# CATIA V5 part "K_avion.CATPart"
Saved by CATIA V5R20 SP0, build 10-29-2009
Part number: avion
Publications: "demi largeur balancier", "epaisseur pieces", "decalage pneu", "Plan.-100", "liaison avion 3/10", "liaison avion 24/28"
Bounding box of the stored display mesh (mm): x -130 to 30, y -769.943 to 389.943, z -50 to 50
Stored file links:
  G:\Khaled_CFAO_2011\SIL\SIL_GR2\mdardier\Khaled\CAD_ThinkMOTION\K_avion.CATPart
  G:\Khaled_CFAO_2011\SIL\SIL_GR2\mdardier\Khaled\CAD_ThinkMOTION\K_ass_tandem.CATProduct
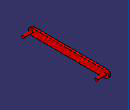
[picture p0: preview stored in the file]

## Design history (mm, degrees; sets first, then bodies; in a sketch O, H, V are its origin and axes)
External parameters (linked from other documents)
  `External.demi largeur balancier` = 50 mm
  `External.epaisseur pieces` = 30 mm
  `External.decalage pneu` = 100 mm
Set1
  Plane1 "Plan.-100": linked copy from another document
  Point1 "liaison avion 3/10": linked copy from another document
  Point2 "liaison avion 24/28": linked copy from another document
Body1 (main body)
  Sketch1 on Plane1, origin (-100, 0, 0), H (0, 1, 0), V (0, 0, 1)
    construction line L1 (-720, 0) -> (340, 0)
    point P1 (-720, 0)
    point P2 (340, 0)
    line L2 (-720, 50) -> (340, 50)
    line L3 (340, -50) -> (-720, -50)
    arc A1 centre (340, 0) radius 50 from (340, 50) to (340, -50) cw
    arc A2 centre (-720, 0) radius 50 from (-720, -50) to (-720, 50) cw
    reference projected point E1 (-720, 0) from Point1
    reference projected point E2 (340, 0) from Point2
    distance L1 L2 = 50 {= `External.demi largeur balancier`}
    tangency: A1 L2, A2 L2, A1 L3, A2 L3
    coincidence: P1 E1, P2 E2
  Pad1: profile Sketch1, direction (-1, 0, 0), length 30 {= `External.epaisseur pieces`}
  Sketch2 on start face of Pad1, origin (-100, 0, 0), H (0, 1, 0), V (0, 0, 1)
    circle A1 centre (-720, 0) radius 20
    point P1 (-720, 0)
    reference projected point E1 (-720, 0) from Point1
    circle A2 centre (340, 0) radius 20
    point P2 (340, 0)
    reference projected point E2 (340, 0) from Point2
    radius A1 = 20 {= `External.demi largeur balancier` *2/5}
    radius A2 = 20 {= `External.demi largeur balancier` *2/5}
    coincidence: P1 E1, P2 E2
  Pad2: profile Sketch2, direction (1, 0, 0), length 130 {= `External.decalage pneu` +`External.epaisseur pieces`}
